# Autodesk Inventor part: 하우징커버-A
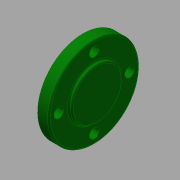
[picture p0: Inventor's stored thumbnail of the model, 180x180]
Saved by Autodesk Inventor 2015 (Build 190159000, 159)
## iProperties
Created: 2018-01
Part Number: 하우징커버-A
Material: 알루미늄 6061
Document SubType Name: Modeling
Designer: mduedu
Density: 2.71 g/cm^3
Appearance: 진녹색
Mass: 8.99967 g
Surface Area: 21.1948 cm^2
Volume: 3.32091 cm^3
Author: mduedu
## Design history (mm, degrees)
sketch "스케치1"
  geometry: C1 r 16 at (0, 0); 1 further point
  constraints: 1 centre point, 1 coincident
  dimensions: "d0" = 32 diameter of C1
extrude "돌출1" new body sketch "스케치1" distance "d1" = 4; taper "d2" = 0 deg
sketch "스케치2"
  geometry: C1 r 9 at (0, 0); 1 further point
  constraints: 1 centre point, 1 coincident
  dimensions: "d3" = 18 diameter of C1
extrude "돌출2" join sketch "스케치2" distance "d4" = 1; taper "d5" = 0 deg
fillet "모깎기1" dims "d6" = 0.5
fillet "모깎기2" dims "d7" = 0.5
sketch "스케치3" dims "d8" = 25
  geometry: 6 further points
  constraints: 2 vertical alignment, 1 coincident, 7 other
  dimensions: "d11" = 360 deg dimension on point (0, 0) point (0, 12.5) (derived)
sketch "스케치4"
  geometry: 4 further points
  constraints: 4 other
hole "구멍1" sketch "스케치4" at (-12.5, 0), (0, -12.5), (12.5, 0), (0, 12.5) diameter "d13" = 3.4; stored, may be unused: countersink angle "d17" = 90 deg, drill point angle "d19" = 0 deg; dims "d14" = 6, "d15" = 4, "d16" = 2, "d18" = 8
node "솔리드1"
